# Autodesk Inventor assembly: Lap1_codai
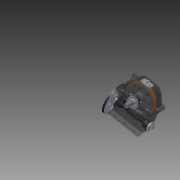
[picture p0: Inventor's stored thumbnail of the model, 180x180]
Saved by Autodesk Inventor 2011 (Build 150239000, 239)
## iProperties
Created: 2011-05
Part Number: Lap1_codai
Document SubType Name: Assembly
Designer: 904Chiaki
Author: 904Chiaki
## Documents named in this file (38)
- E:\2.FINISH\DOAN_CTM_final\Lap_Codai.iam
- E:\2.FINISH\DOAN_CTM_final\Thanhop.ipt
- E:\2.FINISH\DOAN_CTM_final\Shaft1.ipt
- E:\2.FINISH\DOAN_CTM_final\Bearing1.ipt
- E:\2.FINISH\DOAN_CTM_final\Bearing2_1.ipt
- E:\2.FINISH\DOAN_CTM_final\Bearing2_2.ipt
- E:\2.FINISH\DOAN_CTM_final\Bearing3.ipt
- E:\2.FINISH\DOAN_CTM_final\BoTruyenDai.iam
- E:\2.FINISH\DOAN_CTM_final\Naphop.ipt
- E:\2.FINISH\DOAN_CTM_final\Napquansat.ipt
- E:\2.FINISH\DOAN_CTM_final\Nutthonghoi.iam
- E:\2.FINISH\DOAN_CTM_final\Chotdinhvi.ipt
- E:\2.FINISH\DOAN_CTM_final\Bulongbich.ipt
- E:\2.FINISH\DOAN_CTM_final\Daiocbich.ipt
- E:\2.FINISH\DOAN_CTM_final\Vongdembich.ipt
- E:\2.FINISH\DOAN_CTM_final\BulongCanhO.ipt
- E:\2.FINISH\DOAN_CTM_final\Daioccanho.ipt
- E:\2.FINISH\DOAN_CTM_final\VongdemcanhO.ipt
- E:\2.FINISH\DOAN_CTM_final\Vitghepnapcuatham.ipt
- E:\2.FINISH\DOAN_CTM_final\VongChandau2.ipt
- E:\2.FINISH\DOAN_CTM_final\Shaft3.ipt
- E:\2.FINISH\DOAN_CTM_final\Onglot.ipt
- E:\2.FINISH\DOAN_CTM_final\VongChandau1.ipt
- E:\2.FINISH\DOAN_CTM_final\Lap1_codai\Design Accelerator\Key Connection2.iam
- E:\2.FINISH\DOAN_CTM_final\Lap1_codai\Design Accelerator\Key Connection3.iam
- E:\2.FINISH\DOAN_CTM_final\Trucvit.iam
- E:\2.FINISH\DOAN_CTM_final\Coclot1.ipt
- E:\2.FINISH\DOAN_CTM_final\Coclot2.ipt
- E:\2.FINISH\DOAN_CTM_final\NapO2.ipt
- E:\2.FINISH\DOAN_CTM_final\NapO2_2.ipt
- E:\2.FINISH\DOAN_CTM_final\Vongphot2.ipt
- E:\2.FINISH\DOAN_CTM_final\VongdemnapO2.ipt
- E:\2.FINISH\DOAN_CTM_final\NapO1.ipt
- E:\2.FINISH\DOAN_CTM_final\NapO1_2.ipt
- E:\2.FINISH\DOAN_CTM_final\VongdemNapO1.ipt
- E:\2.FINISH\DOAN_CTM_final\Vongphot1.ipt
- E:\2.FINISH\DOAN_CTM_final\VitghepnapO.ipt
- E:\2.FINISH\DOAN_CTM_final\Banhvit.iam
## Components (95 placed, 35 different names)
1. Thanhop:1 — Mate:42, Flush:7, Mate:65, Mate:69, Mate:75, Mate:79, Mate:83, Mate:87, Mate:105, Mate:107, Mate:109, Mate:111, Mate:124, Angle:6, Mate:154, Mate:155, Angle:13, Angle:19, Angle:21, Angle:22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
2. Shaft:1 — Mate:3, Flush:1, Mate:6, Flush:2, Mate:37, Mate:38
3. DIN 615 L 25 - 25 x 52 x 15:1 — Mate:3, Flush:1
4. DIN 615 L 25 - 25 x 52 x 15:2 — Mate:6, Flush:2
5. DIN 628 - T1 7208B - 40 x 80 x 18:1 — Mate:179, Mate:180, Mate:182
6. ISO 355 3DB - 40 x 80 x 19.75:1 — Mate:11, Mate:176
7. ISO 355 3DB - 40 x 80 x 19.75:2 — Mate:11, Mate:135, Mate:175, Mate:176, Mate:178
8. ISO 355 2CE - 70 x 110 x 31:1 — Mate:126, Flush:12
9. ISO 355 2CE - 70 x 110 x 31:2 — Mate:123, Flush:13, Mate:128, Mate:130
10. BoTruyenDai:1 [sub-assembly] — Mate:37, Mate:38, Mate:200, Mate:201
11. Naphop:1 — Mate:42, Flush:7, Mate:45, Flush:8, Flush:9, Mate:50, Flush:10, Mate:51, Flush:11, Mate:52, Mate:53, Mate:54, Mate:55, Mate:56, Mate:57, Mate:58, Mate:59, Mate:60, Mate:61, Mate:62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
12. Napquansat:1 — Mate:43, Mate:44, Mate:45, Flush:8, Flush:9, Mate:112, Mate:113, Mate:114, Mate:115, Mate:116, Mate:117, Mate:118, Mate:119
13. Nutthonghoi:2 [sub-assembly] — Mate:43, Mate:44
14. ISO 2338 4 h8 x 55 - B:1 — Mate:51, Flush:11
15. ISO 2338 4 h8 x 55 - B:2 — Mate:50, Flush:10
16. ISO 4014 M14 x 70:1 — Mate:62, Mate:63, Mate:86
17. ISO 7417 M14:1 — Mate:66, Mate:67
18. ISO 7092 ST 14 - 140 HV:1 — Mate:64, Mate:65, Mate:67
19. ISO 4014 M14 x 70:2 — Mate:60, Mate:61, Mate:78
20. ISO 7417 M14:2 — Mate:70, Mate:71
21. ISO 7092 ST 14 - 140 HV:2 — Mate:68, Mate:69, Mate:71
22. ISO 4014 M14 x 70:3 — Mate:58, Mate:59, Mate:74
23. ISO 7417 M14:3 — Mate:72, Mate:73, Mate:74
24. ISO 7092 ST 14 - 140 HV:3 — Mate:72, Mate:73, Mate:75
25. ISO 4014 M14 x 70:4 — Mate:56, Mate:57, Mate:64, Mate:66
26. ISO 7417 M14:4 — Mate:76, Mate:77, Mate:78
27. ISO 7092 ST 14 - 140 HV:4 — Mate:76, Mate:77, Mate:79
28. ISO 4014 M14 x 70:5 — Mate:54, Mate:55, Mate:82
29. ISO 7417 M14:5 — Mate:80, Mate:81, Mate:82
30. ISO 7092 ST 14 - 140 HV:5 — Mate:80, Mate:81, Mate:83
31. ISO 4014 M14 x 70:6 — Mate:52, Mate:53, Mate:68, Mate:70
32. ISO 7417 M14:6 — Mate:84, Mate:85, Mate:86
33. ISO 7092 ST 14 - 140 HV:6 — Mate:84, Mate:85, Mate:87
34. ISO 4014 M16 x 120:1 — Mate:93, Mate:94, Mate:106
35. ISO 7414 M16:1 — Mate:96, Mate:97, Mate:104
36. ISO 7092 ST 16 - 140 HV:1 — Mate:96, Mate:97, Mate:105
37. ISO 4014 M16 x 120:2 — Mate:92, Mate:95, Mate:104
38. ISO 7414 M16:2 — Mate:98, Mate:99, Mate:106
39. ISO 7092 ST 16 - 140 HV:2 — Mate:98, Mate:99, Mate:107
40. ISO 4014 M16 x 120:3 — Mate:90, Mate:91, Mate:110
41. ISO 7414 M16:3 — Mate:100, Mate:101, Mate:108
42. ISO 7092 ST 16 - 140 HV:3 — Mate:100, Mate:101, Mate:109
43. ISO 4014 M16 x 120:4 — Mate:88, Mate:89, Mate:108
44. ISO 7414 M16:4 — Mate:102, Mate:103, Mate:110
45. ISO 7092 ST 16 - 140 HV:4 — Mate:102, Mate:103, Mate:111
46. ISO 4017 M10 x 20:1 — Mate:112, Mate:113
47. ISO 4017 M10 x 20:2 — Mate:114, Mate:117
48. ISO 4017 M10 x 20:3 — Mate:115, Mate:118
49. ISO 4017 M10 x 20:4 — Mate:116, Mate:119
50. VongChandau2:1 — Mate:127, Mate:129
51. VongChandau2:2 — Mate:123, Mate:130, Mate:131, Mate:133
52. Shaft:3 — Mate:124, Mate:126, Mate:127, Flush:12, Flush:13, Mate:128, Angle:6, Mate:129, Mate:131, Mate:132, Flush:14, Angle:11, Mate:140, Mate:157, Mate:158, Mate:161, Angle:25, Mate:246, Mate:248
53. Onglot:1 — Mate:132, Mate:133
54. VongChandau1:1 — Mate:181, Mate:182
55. VongChandau1:2 — Mate:135, Mate:183
56. Key Connection:1 [sub-assembly]
57. Key Connection:2 [sub-assembly] — Flush:14, Angle:11, Mate:140, Mate:247
58. Trucvit:1 [sub-assembly] — Mate:175, Mate:177, Mate:178, Mate:179, Mate:180, Mate:181, Mate:183, Mate:184, Mate:187, Mate:188, Angle:25, Mate:200, Mate:201
59. Coclot1:1 — Mate:184, Mate:185, Mate:186, Angle:23, Angle:24
60. Coclot2:1 — Mate:154, Mate:155, Angle:13, Mate:166, Mate:167, Mate:173
61. NapO2:1 — Mate:159, Angle:18, Mate:164, Mate:214, Mate:215, Mate:216, Mate:217, Mate:218, Mate:219, Mate:232, Mate:233, Mate:234, Mate:235, Mate:236, Mate:237
62. NapO2_2:1 — Mate:156, Tangent:1, Angle:15, Mate:165, Mate:202, Mate:203, Mate:204, Mate:205, Mate:206, Mate:207, Mate:244, Mate:245
63. Vongphot2:1 — Mate:156, Tangent:1, Mate:157
64. VongdemnapO2:1 — Mate:160, Mate:161, Angle:16, Mate:165
65. VongdemnapO2:2 — Mate:162, Mate:163, Angle:17, Mate:164
66. NapO1:1 — Mate:170, Tangent:2, Angle:21, Mate:188, Mate:189, Mate:208, Mate:209, Mate:210, Mate:211, Mate:212, Mate:213, Mate:238, Mate:239, Mate:240, Mate:241, Mate:242, Mate:243
67. NapO1_2:1 — Mate:173, Mate:174, Angle:22, Mate:220, Mate:221, Mate:222, Mate:223, Mate:224, Mate:225, Mate:226, Mate:227, Mate:228, Mate:229, Mate:230, Mate:231
68. VongdemNapO1:1 — Mate:186, Mate:187, Angle:24, Mate:189
69. Vongphot1:1 — Mate:170, Tangent:2
70. VongdemNapO1:2 — Mate:166, Mate:167, Angle:19, Mate:174
71. ISO 4017 M10 x 25:1 — Mate:220, Mate:230
72. ISO 4017 M10 x 25:2 — Mate:225, Mate:228
73. ISO 4017 M10 x 25:3 — Mate:224, Mate:227
74. ISO 4017 M10 x 25:4 — Mate:223, Mate:226
75. ISO 4017 M10 x 25:5 — Mate:222, Mate:229
76. ISO 4017 M10 x 25:6 — Mate:221, Mate:231
77. ISO 4017 M10 x 25:7 — Mate:214, Mate:236
78. ISO 4017 M10 x 25:8 — Mate:215, Mate:235
79. ISO 4017 M10 x 25:9 — Mate:216, Mate:234
80. ISO 4017 M10 x 25:10 — Mate:217, Mate:232
81. ISO 4017 M10 x 25:11 — Mate:218, Mate:233
82. ISO 4017 M10 x 25:12 — Mate:219, Mate:237
83. ISO 4017 M10 x 25:13 — Mate:208, Mate:242
84. ISO 4017 M10 x 25:14 — Mate:209, Mate:243
85. ISO 4017 M10 x 25:15 — Mate:210, Mate:238
86. ISO 4017 M10 x 25:16 — Mate:211, Mate:241
87. ISO 4017 M10 x 25:17 — Mate:212, Mate:240
88. ISO 4017 M10 x 25:18 — Mate:213, Mate:239
89. ISO 4017 M10 x 25:19 — Mate:202, Flush:19, Mate:245
90. ISO 4017 M10 x 25:20 — Mate:207, Flush:16, Flush:18
91. ISO 4017 M10 x 25:21 — Mate:206, Flush:16, Flush:17
92. ISO 4017 M10 x 25:22 — Mate:205, Flush:17
93. ISO 4017 M10 x 25:23 — Mate:204, Mate:244
94. ISO 4017 M10 x 25:24 — Mate:203, Flush:18, Flush:19
95. Banhvit:1 [sub-assembly] — Mate:246, Mate:247, Mate:248
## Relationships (201: Mate 172, Flush 14, Angle 13, Tangent 2)
- Mate:3: Shaft:1 ↔ DIN 615 L 25 - 25 x 52 x 15:1
- Flush:1: Shaft:1 ↔ DIN 615 L 25 - 25 x 52 x 15:1
- Mate:6: Shaft:1 ↔ DIN 615 L 25 - 25 x 52 x 15:2
- Flush:2: Shaft:1 ↔ DIN 615 L 25 - 25 x 52 x 15:2
- Mate:11: ISO 355 3DB - 40 x 80 x 19.75:1 ↔ ISO 355 3DB - 40 x 80 x 19.75:2
- Mate:37: Shaft:1 ↔ BoTruyenDai:1
- Mate:38: Shaft:1 ↔ BoTruyenDai:1
- Mate:42: Thanhop:1 ↔ Naphop:1
- Flush:7: Thanhop:1 ↔ Naphop:1
- Mate:43: Napquansat:1 ↔ Nutthonghoi:2
- Mate:44: Napquansat:1 ↔ Nutthonghoi:2
- Mate:45: Naphop:1 ↔ Napquansat:1
- Flush:8: Naphop:1 ↔ Napquansat:1
- Flush:9: Naphop:1 ↔ Napquansat:1
- Mate:50: Naphop:1 ↔ ISO 2338 4 h8 x 55 - B:2
- Flush:10: Naphop:1 ↔ ISO 2338 4 h8 x 55 - B:2
- Mate:51: Naphop:1 ↔ ISO 2338 4 h8 x 55 - B:1
- Flush:11: Naphop:1 ↔ ISO 2338 4 h8 x 55 - B:1
- Mate:52: Naphop:1 ↔ ISO 4014 M14 x 70:6
- Mate:53: Naphop:1 ↔ ISO 4014 M14 x 70:6
- Mate:54: Naphop:1 ↔ ISO 4014 M14 x 70:5
- Mate:55: Naphop:1 ↔ ISO 4014 M14 x 70:5
- Mate:56: Naphop:1 ↔ ISO 4014 M14 x 70:4
- Mate:57: Naphop:1 ↔ ISO 4014 M14 x 70:4
- Mate:58: Naphop:1 ↔ ISO 4014 M14 x 70:3
- Mate:59: Naphop:1 ↔ ISO 4014 M14 x 70:3
- Mate:60: Naphop:1 ↔ ISO 4014 M14 x 70:2
- Mate:61: Naphop:1 ↔ ISO 4014 M14 x 70:2
- Mate:62: Naphop:1 ↔ ISO 4014 M14 x 70:1
- Mate:63: Naphop:1 ↔ ISO 4014 M14 x 70:1
- Mate:64: ISO 7092 ST 14 - 140 HV:1 ↔ ISO 4014 M14 x 70:4
- Mate:65: Thanhop:1 ↔ ISO 7092 ST 14 - 140 HV:1
- Mate:66: ISO 7417 M14:1 ↔ ISO 4014 M14 x 70:4
- Mate:67: ISO 7417 M14:1 ↔ ISO 7092 ST 14 - 140 HV:1
- Mate:68: ISO 7092 ST 14 - 140 HV:2 ↔ ISO 4014 M14 x 70:6
- Mate:69: Thanhop:1 ↔ ISO 7092 ST 14 - 140 HV:2
- Mate:70: ISO 7417 M14:2 ↔ ISO 4014 M14 x 70:6
- Mate:71: ISO 7417 M14:2 ↔ ISO 7092 ST 14 - 140 HV:2
- Mate:72: ISO 7417 M14:3 ↔ ISO 7092 ST 14 - 140 HV:3
- Mate:73: ISO 7417 M14:3 ↔ ISO 7092 ST 14 - 140 HV:3
- Mate:74: ISO 4014 M14 x 70:3 ↔ ISO 7417 M14:3
- Mate:75: Thanhop:1 ↔ ISO 7092 ST 14 - 140 HV:3
- Mate:76: ISO 7417 M14:4 ↔ ISO 7092 ST 14 - 140 HV:4
- Mate:77: ISO 7417 M14:4 ↔ ISO 7092 ST 14 - 140 HV:4
- Mate:78: ISO 4014 M14 x 70:2 ↔ ISO 7417 M14:4
- Mate:79: Thanhop:1 ↔ ISO 7092 ST 14 - 140 HV:4
- Mate:80: ISO 7417 M14:5 ↔ ISO 7092 ST 14 - 140 HV:5
- Mate:81: ISO 7417 M14:5 ↔ ISO 7092 ST 14 - 140 HV:5
- Mate:82: ISO 4014 M14 x 70:5 ↔ ISO 7417 M14:5
- Mate:83: Thanhop:1 ↔ ISO 7092 ST 14 - 140 HV:5
- Mate:84: ISO 7417 M14:6 ↔ ISO 7092 ST 14 - 140 HV:6
- Mate:85: ISO 7417 M14:6 ↔ ISO 7092 ST 14 - 140 HV:6
- Mate:86: ISO 4014 M14 x 70:1 ↔ ISO 7417 M14:6
- Mate:87: Thanhop:1 ↔ ISO 7092 ST 14 - 140 HV:6
- Mate:88: Naphop:1 ↔ ISO 4014 M16 x 120:4
- Mate:89: Naphop:1 ↔ ISO 4014 M16 x 120:4
- Mate:90: Naphop:1 ↔ ISO 4014 M16 x 120:3
- Mate:91: Naphop:1 ↔ ISO 4014 M16 x 120:3
- Mate:92: Naphop:1 ↔ ISO 4014 M16 x 120:2
- Mate:93: Naphop:1 ↔ ISO 4014 M16 x 120:1
- Mate:94: Naphop:1 ↔ ISO 4014 M16 x 120:1
- Mate:95: Naphop:1 ↔ ISO 4014 M16 x 120:2
- Mate:96: ISO 7414 M16:1 ↔ ISO 7092 ST 16 - 140 HV:1
- Mate:97: ISO 7414 M16:1 ↔ ISO 7092 ST 16 - 140 HV:1
- Mate:98: ISO 7414 M16:2 ↔ ISO 7092 ST 16 - 140 HV:2
- Mate:99: ISO 7414 M16:2 ↔ ISO 7092 ST 16 - 140 HV:2
- Mate:100: ISO 7414 M16:3 ↔ ISO 7092 ST 16 - 140 HV:3
- Mate:101: ISO 7414 M16:3 ↔ ISO 7092 ST 16 - 140 HV:3
- Mate:102: ISO 7414 M16:4 ↔ ISO 7092 ST 16 - 140 HV:4
- Mate:103: ISO 7414 M16:4 ↔ ISO 7092 ST 16 - 140 HV:4
- Mate:104: ISO 7414 M16:1 ↔ ISO 4014 M16 x 120:2
- Mate:105: Thanhop:1 ↔ ISO 7092 ST 16 - 140 HV:1
- Mate:106: ISO 4014 M16 x 120:1 ↔ ISO 7414 M16:2
- Mate:107: Thanhop:1 ↔ ISO 7092 ST 16 - 140 HV:2
- Mate:108: ISO 7414 M16:3 ↔ ISO 4014 M16 x 120:4
- Mate:109: Thanhop:1 ↔ ISO 7092 ST 16 - 140 HV:3
- Mate:110: ISO 4014 M16 x 120:3 ↔ ISO 7414 M16:4
- Mate:111: Thanhop:1 ↔ ISO 7092 ST 16 - 140 HV:4
- Mate:112: Napquansat:1 ↔ ISO 4017 M10 x 20:1
- Mate:113: Napquansat:1 ↔ ISO 4017 M10 x 20:1
- Mate:114: Napquansat:1 ↔ ISO 4017 M10 x 20:2
- Mate:115: Napquansat:1 ↔ ISO 4017 M10 x 20:3
- Mate:116: Napquansat:1 ↔ ISO 4017 M10 x 20:4
- Mate:117: Napquansat:1 ↔ ISO 4017 M10 x 20:2
- Mate:118: Napquansat:1 ↔ ISO 4017 M10 x 20:3
- Mate:119: Napquansat:1 ↔ ISO 4017 M10 x 20:4
- Mate:123: ISO 355 2CE - 70 x 110 x 31:2 ↔ VongChandau2:2
- Mate:124: Thanhop:1 ↔ Shaft:3
- Mate:126: ISO 355 2CE - 70 x 110 x 31:1 ↔ Shaft:3
- Mate:127: VongChandau2:1 ↔ Shaft:3
- Flush:12: ISO 355 2CE - 70 x 110 x 31:1 ↔ Shaft:3
- Flush:13: ISO 355 2CE - 70 x 110 x 31:2 ↔ Shaft:3
- Mate:128: ISO 355 2CE - 70 x 110 x 31:2 ↔ Shaft:3
- Angle:6: Thanhop:1 ↔ Shaft:3
- Mate:129: VongChandau2:1 ↔ Shaft:3
- Mate:130: ISO 355 2CE - 70 x 110 x 31:2 ↔ VongChandau2:2
- Mate:131: VongChandau2:2 ↔ Shaft:3
- Mate:132: Shaft:3 ↔ Onglot:1
- Mate:133: VongChandau2:2 ↔ Onglot:1
- Mate:135: ISO 355 3DB - 40 x 80 x 19.75:2 ↔ VongChandau1:2
- Flush:14: Shaft:3 ↔ Key Connection:2
- Angle:11: Shaft:3 ↔ Key Connection:2
- Mate:140: Shaft:3 ↔ Key Connection:2
- Mate:154: Thanhop:1 ↔ Coclot2:1
- Mate:155: Thanhop:1 ↔ Coclot2:1
- Angle:13: Thanhop:1 ↔ Coclot2:1
- Mate:156: NapO2_2:1 ↔ Vongphot2:1
- Tangent:1: NapO2_2:1 ↔ Vongphot2:1
- Mate:157: Shaft:3 ↔ Vongphot2:1
- Mate:158: Naphop:1 ↔ Shaft:3
- Angle:15: Naphop:1 ↔ NapO2_2:1
- Mate:159: Naphop:1 ↔ NapO2:1
- Mate:160: Naphop:1 ↔ VongdemnapO2:1
- Mate:161: Shaft:3 ↔ VongdemnapO2:1
- Angle:16: Naphop:1 ↔ VongdemnapO2:1
- Mate:162: Naphop:1 ↔ VongdemnapO2:2
- Mate:163: Naphop:1 ↔ VongdemnapO2:2
- Angle:17: Naphop:1 ↔ VongdemnapO2:2
- Angle:18: Naphop:1 ↔ NapO2:1
- Mate:164: NapO2:1 ↔ VongdemnapO2:2
- Mate:165: NapO2_2:1 ↔ VongdemnapO2:1
- Mate:166: Coclot2:1 ↔ VongdemNapO1:2
- Mate:167: Coclot2:1 ↔ VongdemNapO1:2
- Angle:19: Thanhop:1 ↔ VongdemNapO1:2
- Mate:170: NapO1:1 ↔ Vongphot1:1
- Tangent:2: NapO1:1 ↔ Vongphot1:1
- Angle:21: Thanhop:1 ↔ NapO1:1
- Mate:173: Coclot2:1 ↔ NapO1_2:1
- Mate:174: NapO1_2:1 ↔ VongdemNapO1:2
- Angle:22: Thanhop:1 ↔ NapO1_2:1
- Mate:175: ISO 355 3DB - 40 x 80 x 19.75:2 ↔ Trucvit:1
- Mate:176: ISO 355 3DB - 40 x 80 x 19.75:1 ↔ ISO 355 3DB - 40 x 80 x 19.75:2
- Mate:177: Thanhop:1 ↔ Trucvit:1
- Mate:178: ISO 355 3DB - 40 x 80 x 19.75:2 ↔ Trucvit:1
- Mate:179: DIN 628 - T1 7208B - 40 x 80 x 18:1 ↔ Trucvit:1
- Mate:180: DIN 628 - T1 7208B - 40 x 80 x 18:1 ↔ Trucvit:1
- Mate:181: VongChandau1:1 ↔ Trucvit:1
- Mate:182: DIN 628 - T1 7208B - 40 x 80 x 18:1 ↔ VongChandau1:1
- Mate:183: VongChandau1:2 ↔ Trucvit:1
- Mate:184: Trucvit:1 ↔ Coclot1:1
- Mate:185: Thanhop:1 ↔ Coclot1:1
- Mate:186: Coclot1:1 ↔ VongdemNapO1:1
- Mate:187: Trucvit:1 ↔ VongdemNapO1:1
- Angle:23: Thanhop:1 ↔ Coclot1:1
- Angle:24: Coclot1:1 ↔ VongdemNapO1:1
- Mate:188: Trucvit:1 ↔ NapO1:1
- Mate:189: NapO1:1 ↔ VongdemNapO1:1
- Angle:25: Shaft:3 ↔ Trucvit:1
- Mate:200: BoTruyenDai:1 ↔ Trucvit:1
- Mate:201: BoTruyenDai:1 ↔ Trucvit:1
- Mate:202: NapO2_2:1 ↔ ISO 4017 M10 x 25:19
- Mate:203: NapO2_2:1 ↔ ISO 4017 M10 x 25:24
- Mate:204: NapO2_2:1 ↔ ISO 4017 M10 x 25:23
- Mate:205: NapO2_2:1 ↔ ISO 4017 M10 x 25:22
- Mate:206: NapO2_2:1 ↔ ISO 4017 M10 x 25:21
- Mate:207: NapO2_2:1 ↔ ISO 4017 M10 x 25:20
- Mate:208: NapO1:1 ↔ ISO 4017 M10 x 25:13
- Mate:209: NapO1:1 ↔ ISO 4017 M10 x 25:14
- Mate:210: NapO1:1 ↔ ISO 4017 M10 x 25:15
- Mate:211: NapO1:1 ↔ ISO 4017 M10 x 25:16
- Mate:212: NapO1:1 ↔ ISO 4017 M10 x 25:17
- Mate:213: NapO1:1 ↔ ISO 4017 M10 x 25:18
- Mate:214: NapO2:1 ↔ ISO 4017 M10 x 25:7
- Mate:215: NapO2:1 ↔ ISO 4017 M10 x 25:8
- Mate:216: NapO2:1 ↔ ISO 4017 M10 x 25:9
- Mate:217: NapO2:1 ↔ ISO 4017 M10 x 25:10
- Mate:218: NapO2:1 ↔ ISO 4017 M10 x 25:11
- Mate:219: NapO2:1 ↔ ISO 4017 M10 x 25:12
- Mate:220: NapO1_2:1 ↔ ISO 4017 M10 x 25:1
- Mate:221: NapO1_2:1 ↔ ISO 4017 M10 x 25:6
- Mate:222: NapO1_2:1 ↔ ISO 4017 M10 x 25:5
- Mate:223: NapO1_2:1 ↔ ISO 4017 M10 x 25:4
- Mate:224: NapO1_2:1 ↔ ISO 4017 M10 x 25:3
- Mate:225: NapO1_2:1 ↔ ISO 4017 M10 x 25:2
- Mate:226: NapO1_2:1 ↔ ISO 4017 M10 x 25:4
- Mate:227: NapO1_2:1 ↔ ISO 4017 M10 x 25:3
- Mate:228: NapO1_2:1 ↔ ISO 4017 M10 x 25:2
- Mate:229: NapO1_2:1 ↔ ISO 4017 M10 x 25:5
- Mate:230: NapO1_2:1 ↔ ISO 4017 M10 x 25:1
- Mate:231: NapO1_2:1 ↔ ISO 4017 M10 x 25:6
- Mate:232: NapO2:1 ↔ ISO 4017 M10 x 25:10
- Mate:233: NapO2:1 ↔ ISO 4017 M10 x 25:11
- Mate:234: NapO2:1 ↔ ISO 4017 M10 x 25:9
- Mate:235: NapO2:1 ↔ ISO 4017 M10 x 25:8
- Mate:236: NapO2:1 ↔ ISO 4017 M10 x 25:7
- Mate:237: NapO2:1 ↔ ISO 4017 M10 x 25:12
- Mate:238: NapO1:1 ↔ ISO 4017 M10 x 25:15
- Mate:239: NapO1:1 ↔ ISO 4017 M10 x 25:18
- Mate:240: NapO1:1 ↔ ISO 4017 M10 x 25:17
- Mate:241: NapO1:1 ↔ ISO 4017 M10 x 25:16
- Mate:242: NapO1:1 ↔ ISO 4017 M10 x 25:13
- Mate:243: NapO1:1 ↔ ISO 4017 M10 x 25:14
- Mate:244: NapO2_2:1 ↔ ISO 4017 M10 x 25:23
- Flush:16: ISO 4017 M10 x 25:20 ↔ ISO 4017 M10 x 25:21
- Flush:17: ISO 4017 M10 x 25:21 ↔ ISO 4017 M10 x 25:22
- Flush:18: ISO 4017 M10 x 25:20 ↔ ISO 4017 M10 x 25:24
- Flush:19: ISO 4017 M10 x 25:19 ↔ ISO 4017 M10 x 25:24
- Mate:245: NapO2_2:1 ↔ ISO 4017 M10 x 25:19
- Mate:246: Shaft:3 ↔ Banhvit:1
- Mate:247: Key Connection:2 ↔ Banhvit:1
- Mate:248: Shaft:3 ↔ Banhvit:1
